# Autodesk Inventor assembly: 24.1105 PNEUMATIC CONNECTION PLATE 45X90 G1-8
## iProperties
Created: 2007-06
Part Number: 24.1105 PNEUMATIC CONNECTION PLATE 45X90 G1-8
Document SubType Name: Assembly
Designer: Andy Moles
Author: Andy Moles
